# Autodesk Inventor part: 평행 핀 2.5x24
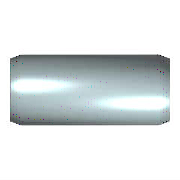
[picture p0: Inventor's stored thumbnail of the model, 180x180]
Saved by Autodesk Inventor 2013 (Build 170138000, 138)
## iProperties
IsCustomPart: 1
Created: 2012-02
Part Number: 평행 핀 2.5x24
Material: 강철, 연강
Description: 평행 핀
Document SubType Name: Modeling
Standard: KS B 1320
Designer: mduedu
Standards Organization: KS
Language: ko-KR
Size Designation: B 2.5 x  24
Categories: <MemberInstance><Categories><Category DisplayName="조임쇠" InternalName="e4da775c-781d-43d5-af7c-5136215cf5a6" Mnemonic="FSTN"><Category DisplayName="핀" InternalNa
Density: 1 g/cm^3
Author: mduedu
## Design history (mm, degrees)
sketch "스케치"
  geometry: C1 r 1.25 at (0, 0); 1 further point
  constraints: 1 centre point, 1 coincident
  dimensions: "d1" = 2.5 diameter of C1 (= NND)
extrude "본체" new body sketch "스케치" distance "d2" = 24 (= NLG); taper "d3" = 0 deg
chamfer "스케치2" distance "d8" = 0.4 (= PHH); stored, may be unused: angle "d9" = 15 deg (= FAWI), second distance "d12" = 0.4 (= PHH)
node "작업 평면1"
body "Solid1"
chamfer "모따기1" distance "d4" = 0.4 (= PHH); stored, may be unused: angle "d5" = 15 deg (= FAWI), second distance "d11" = 0.4 (= PHH)
other parameters: "NND" = 2.5 [user parameter; used in 1 equation term], "NLG" = 24 [user parameter; used in 1 equation term], "PHH" = 0.4 [user parameter; used in 4 equation terms], "FAWI" = 15 deg [user parameter; used in 2 equation terms], "d13" = 0, "d15" = 0, "d16" = 0, "KAH" = 0.3 [user parameter]
